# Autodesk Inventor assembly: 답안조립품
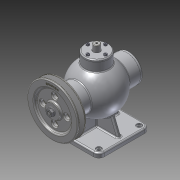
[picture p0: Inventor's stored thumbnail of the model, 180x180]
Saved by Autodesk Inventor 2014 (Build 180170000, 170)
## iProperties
Created: 2015-10
Part Number: 답안조립품
Document SubType Name: Assembly
Designer: youjin22
Author: youjin22
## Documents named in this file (19)
- C:\Users\youjin22\Desktop\451010V1011\답안조립품.iam
- C:\Users\youjin22\Desktop\451010V1011\본체.ipt
- C:\Users\youjin22\Desktop\451010V1011\앞커버.ipt
- C:\Users\youjin22\Desktop\451010V1011\오일실 15 30 7.ipt
- C:\Users\youjin22\Desktop\451010V1011\볼트 M4 x 16.ipt
- C:\Users\youjin22\Desktop\451010V1011\베어링- 6202.ipt
- KS B 2023 - 6202 - 15 x 35 x 11 - 7.8.ipt
- C:\Users\youjin22\Desktop\451010V1011\편심축.ipt
- C:\Users\youjin22\Desktop\451010V1011\부시.ipt
- C:\Users\youjin22\Desktop\451010V1011\뒤커버.ipt
- C:\Users\youjin22\Desktop\451010V1011\멈춤링- 15 x 1.ipt
- C:\Users\youjin22\Desktop\451010V1011\멈춤링- 35x1.6.ipt
- KS B 1336 - 35x1.6.ipt
- C:\Users\youjin22\Desktop\451010V1011\상부커버.ipt
- C:\Users\youjin22\Desktop\451010V1011\볼트 M 4 x 12.ipt
- C:\Users\youjin22\Desktop\451010V1011\키 4 x 4 x 12.ipt
- C:\Users\youjin22\Desktop\451010V1011\V-벨트풀리.ipt
- C:\Users\youjin22\Desktop\451010V1011\너트 M8.ipt
- C:\Users\youjin22\Desktop\451010V1011\슬라이드.ipt
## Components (16 placed, 5 different names)
1. KS B 2023 - 6202 - 15 x 35 x 11 - 7.8:1 — 각도:1
2. KS B 2023 - 6202 - 15 x 35 x 11 - 7.8:2 — 각도:4
3. KS B 1336 - 35x1.6:1 — 각도:5
4. V-벨트풀리:1
5. ISO 4762 M4 x 16:1
6. ISO 4762 M4 x 16:2
7. ISO 4762 M4 x 16:3
8. ISO 4762 M4 x 16:4
9. ISO 4762 M4 x 16:5
10. ISO 4762 M4 x 16:6
11. ISO 4762 M4 x 16:7
12. ISO 4762 M4 x 16:8
13. KS B 1021 - 에 따름 ISO 1207 - 미터 A  M 4 x 12:1
14. KS B 1021 - 에 따름 ISO 1207 - 미터 A  M 4 x 12:2
15. KS B 1021 - 에 따름 ISO 1207 - 미터 A  M 4 x 12:3
16. KS B 1021 - 에 따름 ISO 1207 - 미터 A  M 4 x 12:4
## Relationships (3: Angle 3)
- 각도:1 [Angle]: KS B 2023 - 6202 - 15 x 35 x 11 - 7.8:1
- 각도:4 [Angle]: KS B 2023 - 6202 - 15 x 35 x 11 - 7.8:2
- 각도:5 [Angle]: KS B 1336 - 35x1.6:1
